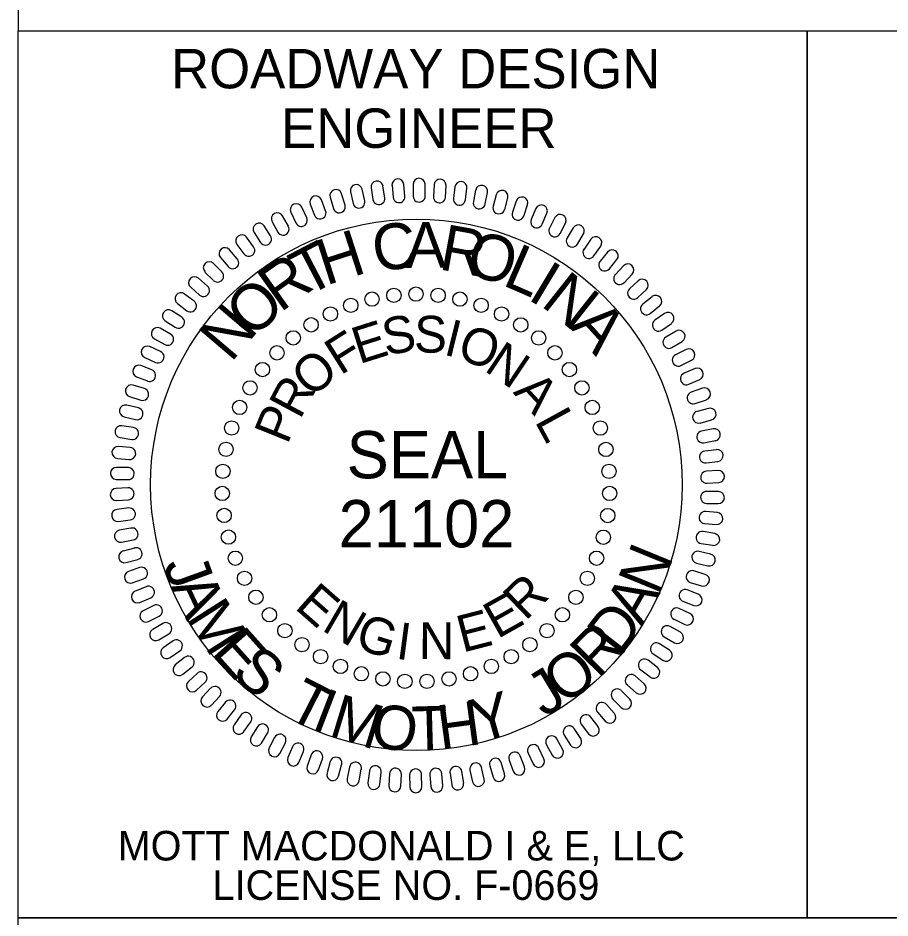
# Model space of a CAD drawing. Extents: x 1901670 to 1902225, y 193498 to 194278.
# Drawn here: x 1902112.54 to 1902123.59, y 194250.51 to 194261.92 of the extents above; entities that cross this region are included whole.
import ezdxf

# ---------------------------------------------------------------- set-up
doc = ezdxf.new("R2010")
doc.units = 0
for name, color, linetype in [('ENG SEALS CELL', 7, 'Continuous'), ('Old_Level_45', 7, 'Continuous'), ('Scratch_Level_3', 7, 'Continuous'), ('Sheet Border Standard 30in CELL', 7, 'Continuous'), ('Sheet Sticker Exception Certification CELL', 7, 'Continuous')]:
    doc.layers.add(name, color=color, linetype=linetype)

msp = doc.modelspace()

# ---------------------------------------------------------------- linework, layer by layer
at = {"layer": 'ENG SEALS CELL'}
for p, q in [((1902117.189, 194259.642), (1902117.166, 194259.789)), ((1902117.281, 194259.798), (1902117.293, 194259.649)), ((1902117.445, 194259.661), (1902117.432, 194259.811)), ((1902117.547, 194259.811), (1902117.549, 194259.661)), ((1902117.701, 194259.663), (1902117.699, 194259.813)), ((1902117.813, 194259.805), (1902117.805, 194259.656)), ((1902117.957, 194259.647), (1902117.965, 194259.797)), ((1902116.685, 194259.548), (1902116.642, 194259.692)), ((1902116.754, 194259.716), (1902116.788, 194259.57)), ((1902116.936, 194259.604), (1902116.902, 194259.75)), ((1902117.016, 194259.766), (1902117.039, 194259.618)), ((1902118.078, 194259.782), (1902118.06, 194259.633)), ((1902118.211, 194259.614), (1902118.229, 194259.762)), ((1902118.341, 194259.739), (1902118.312, 194259.593)), ((1902118.462, 194259.563), (1902118.491, 194259.71)), ((1902118.601, 194259.678), (1902118.562, 194259.534)), ((1902116.244, 194259.562), (1902116.298, 194259.422)), ((1902116.439, 194259.476), (1902116.386, 194259.616)), ((1902116.497, 194259.647), (1902116.539, 194259.504)), ((1902118.709, 194259.494), (1902118.748, 194259.639)), ((1902118.856, 194259.6), (1902118.807, 194259.458)), ((1902115.999, 194259.458), (1902116.061, 194259.322)), ((1902116.2, 194259.386), (1902116.136, 194259.522)), ((1902118.95, 194259.409), (1902119, 194259.55)), ((1902119.105, 194259.504), (1902119.046, 194259.365)), ((1902115.76, 194259.338), (1902115.833, 194259.206)), ((1902115.966, 194259.28), (1902115.894, 194259.411)), ((1902119.185, 194259.306), (1902119.245, 194259.444)), ((1902119.346, 194259.39), (1902119.278, 194259.257)), ((1902115.741, 194259.158), (1902115.66, 194259.284)), ((1902115.741, 194259.158), (1902115.66, 194259.284)), ((1902119.412, 194259.187), (1902119.481, 194259.321)), ((1902119.578, 194259.261), (1902119.501, 194259.132)), ((1902115.524, 194259.02), (1902115.435, 194259.141)), ((1902115.524, 194259.02), (1902115.435, 194259.141)), ((1902115.531, 194259.201), (1902115.613, 194259.075)), ((1902115.531, 194259.201), (1902115.613, 194259.075)), ((1902119.631, 194259.053), (1902119.709, 194259.182)), ((1902119.801, 194259.115), (1902119.716, 194258.991)), ((1902115.313, 194259.049), (1902115.403, 194258.929)), ((1902115.313, 194259.049), (1902115.403, 194258.929)), ((1902119.839, 194258.904), (1902119.926, 194259.026)), ((1902115.105, 194258.882), (1902115.203, 194258.769)), ((1902115.105, 194258.882), (1902115.203, 194258.769)), ((1902115.318, 194258.868), (1902115.22, 194258.982)), ((1902115.318, 194258.868), (1902115.22, 194258.982)), ((1902120.014, 194258.953), (1902119.919, 194258.837)), ((1902115.124, 194258.701), (1902115.018, 194258.808)), ((1902120.037, 194258.741), (1902120.132, 194258.857)), ((1902120.215, 194258.778), (1902120.112, 194258.668)), ((1902114.909, 194258.7), (1902115.015, 194258.595)), ((1902120.223, 194258.564), (1902120.326, 194258.674)), ((1902114.94, 194258.522), (1902114.828, 194258.621)), ((1902120.402, 194258.589), (1902120.292, 194258.487)), ((1902114.77, 194258.331), (1902114.651, 194258.421)), ((1902114.728, 194258.506), (1902114.84, 194258.408)), ((1902120.396, 194258.376), (1902120.506, 194258.478)), ((1902120.577, 194258.387), (1902120.46, 194258.294)), ((1902114.615, 194258.127), (1902114.489, 194258.209)), ((1902114.559, 194258.3), (1902114.679, 194258.209)), ((1902120.555, 194258.175), (1902120.672, 194258.269)), ((1902114.406, 194258.082), (1902114.531, 194258)), ((1902120.737, 194258.174), (1902120.613, 194258.088)), ((1902114.473, 194257.913), (1902114.342, 194257.987)), ((1902120.701, 194257.963), (1902120.823, 194258.049)), ((1902114.268, 194257.854), (1902114.399, 194257.781)), ((1902120.881, 194257.95), (1902120.753, 194257.873)), ((1902114.346, 194257.691), (1902114.211, 194257.754)), ((1902120.83, 194257.743), (1902120.959, 194257.819)), ((1902121.01, 194257.716), (1902120.876, 194257.649)), ((1902114.236, 194257.46), (1902114.096, 194257.514)), ((1902114.146, 194257.616), (1902114.281, 194257.553)), ((1902120.944, 194257.513), (1902121.078, 194257.581)), ((1902121.122, 194257.475), (1902120.983, 194257.417)), ((1902114.042, 194257.372), (1902114.181, 194257.318)), ((1902121.042, 194257.277), (1902121.181, 194257.335)), ((1902114.142, 194257.221), (1902113.999, 194257.265)), ((1902121.216, 194257.226), (1902121.074, 194257.177)), ((1902113.954, 194257.12), (1902114.097, 194257.075)), ((1902121.124, 194257.033), (1902121.266, 194257.081)), ((1902114.065, 194256.977), (1902113.919, 194257.01)), ((1902121.293, 194256.97), (1902121.148, 194256.932)), ((1902113.884, 194256.862), (1902114.03, 194256.829)), ((1902121.187, 194256.785), (1902121.332, 194256.824)), ((1902114.005, 194256.728), (1902113.856, 194256.751)), ((1902121.353, 194256.711), (1902121.205, 194256.683)), ((1902113.833, 194256.601), (1902113.981, 194256.577)), ((1902113.962, 194256.475), (1902113.813, 194256.488)), ((1902121.234, 194256.533), (1902121.381, 194256.562)), ((1902121.394, 194256.447), (1902121.245, 194256.429)), ((1902113.799, 194256.337), (1902113.948, 194256.323)), ((1902121.263, 194256.279), (1902121.412, 194256.296)), ((1902113.937, 194256.22), (1902113.788, 194256.222)), ((1902121.417, 194256.181), (1902121.267, 194256.174)), ((1902113.784, 194256.071), (1902113.934, 194256.067)), ((1902121.274, 194256.022), (1902121.424, 194256.03)), ((1902113.93, 194255.963), (1902113.781, 194255.956)), ((1902121.42, 194255.915), (1902121.27, 194255.918)), ((1902113.788, 194255.804), (1902113.938, 194255.811)), ((1902113.942, 194255.708), (1902113.793, 194255.69)), ((1902121.267, 194255.766), (1902121.417, 194255.763)), ((1902121.405, 194255.649), (1902121.256, 194255.663)), ((1902113.811, 194255.538), (1902113.96, 194255.556)), ((1902113.97, 194255.453), (1902113.823, 194255.425)), ((1902121.242, 194255.511), (1902121.391, 194255.498)), ((1902121.372, 194255.384), (1902121.224, 194255.408)), ((1902113.852, 194255.275), (1902113.999, 194255.303)), ((1902121.199, 194255.258), (1902121.348, 194255.235)), ((1902114.017, 194255.2), (1902113.872, 194255.162)), ((1902121.32, 194255.123), (1902121.174, 194255.157)), ((1902113.911, 194255.015), (1902114.056, 194255.053)), ((1902121.14, 194255.009), (1902121.286, 194254.975)), ((1902114.081, 194254.952), (1902113.939, 194254.904)), ((1902121.25, 194254.866), (1902121.108, 194254.91)), ((1902113.988, 194254.76), (1902114.13, 194254.808)), ((1902114.162, 194254.71), (1902114.024, 194254.651)), ((1902121.163, 194254.614), (1902121.023, 194254.668)), ((1902121.062, 194254.764), (1902121.206, 194254.72)), ((1902114.083, 194254.511), (1902114.221, 194254.57)), ((1902114.26, 194254.473), (1902114.126, 194254.405)), ((1902121.058, 194254.369), (1902120.922, 194254.432)), ((1902120.968, 194254.527), (1902121.108, 194254.473)), ((1902114.195, 194254.269), (1902114.329, 194254.336)), ((1902114.375, 194254.244), (1902114.246, 194254.166)), ((1902120.937, 194254.132), (1902120.806, 194254.205)), ((1902120.858, 194254.296), (1902120.994, 194254.232)), ((1902114.324, 194254.036), (1902114.452, 194254.112)), ((1902114.504, 194254.022), (1902114.381, 194253.936)), ((1902120.799, 194253.904), (1902120.673, 194253.986)), ((1902120.732, 194254.072), (1902120.863, 194253.999)), ((1902114.468, 194253.812), (1902114.591, 194253.897)), ((1902120.59, 194253.859), (1902120.715, 194253.777)), ((1902114.649, 194253.811), (1902114.532, 194253.717)), ((1902120.645, 194253.686), (1902120.526, 194253.777)), ((1902114.627, 194253.599), (1902114.745, 194253.693)), ((1902120.434, 194253.656), (1902120.553, 194253.565)), ((1902114.808, 194253.61), (1902114.699, 194253.508)), ((1902120.477, 194253.479), (1902120.364, 194253.578)), ((1902114.802, 194253.397), (1902114.911, 194253.499)), ((1902114.981, 194253.421), (1902114.879, 194253.312)), ((1902120.264, 194253.463), (1902120.377, 194253.365)), ((1902114.99, 194253.208), (1902115.092, 194253.317)), ((1902120.081, 194253.284), (1902120.186, 194253.178)), ((1902120.295, 194253.285), (1902120.188, 194253.391)), ((1902115.168, 194253.245), (1902115.073, 194253.128)), ((1902120.099, 194253.104), (1902120.001, 194253.217)), ((1902115.191, 194253.032), (1902115.285, 194253.149)), ((1902115.365, 194253.082), (1902115.278, 194252.959)), ((1902119.892, 194252.937), (1902119.801, 194253.056)), ((1902119.886, 194253.118), (1902119.984, 194253.004)), ((1902115.403, 194252.872), (1902115.489, 194252.994)), ((1902119.68, 194252.965), (1902119.77, 194252.846)), ((1902115.573, 194252.932), (1902115.496, 194252.805)), ((1902115.626, 194252.726), (1902115.703, 194252.854)), ((1902119.464, 194252.828), (1902119.545, 194252.702)), ((1902119.673, 194252.784), (1902119.591, 194252.91)), ((1902115.792, 194252.798), (1902115.724, 194252.665)), ((1902115.859, 194252.596), (1902115.928, 194252.729)), ((1902119.444, 194252.648), (1902119.371, 194252.779)), ((1902116.019, 194252.68), (1902115.96, 194252.542)), ((1902116.1, 194252.482), (1902116.159, 194252.62)), ((1902119.005, 194252.6), (1902119.068, 194252.464)), ((1902119.206, 194252.527), (1902119.143, 194252.663)), ((1902119.239, 194252.706), (1902119.31, 194252.574)), ((1902116.254, 194252.578), (1902116.205, 194252.436)), ((1902116.349, 194252.386), (1902116.398, 194252.528)), ((1902116.496, 194252.492), (1902116.457, 194252.348)), ((1902118.765, 194252.51), (1902118.818, 194252.37)), ((1902118.961, 194252.424), (1902118.907, 194252.564)), ((1902116.603, 194252.308), (1902116.642, 194252.452)), ((1902116.743, 194252.423), (1902116.713, 194252.276)), ((1902116.863, 194252.246), (1902116.891, 194252.394)), ((1902116.994, 194252.372), (1902116.975, 194252.223)), ((1902118.269, 194252.382), (1902118.302, 194252.236)), ((1902118.45, 194252.27), (1902118.417, 194252.416)), ((1902118.519, 194252.437), (1902118.562, 194252.294)), ((1902118.708, 194252.338), (1902118.664, 194252.481)), ((1902117.126, 194252.204), (1902117.145, 194252.353)), ((1902117.248, 194252.338), (1902117.239, 194252.188)), ((1902117.391, 194252.18), (1902117.4, 194252.33)), ((1902117.503, 194252.322), (1902117.506, 194252.172)), ((1902117.658, 194252.175), (1902117.655, 194252.325)), ((1902117.76, 194252.324), (1902117.773, 194252.175)), ((1902117.924, 194252.188), (1902117.911, 194252.337)), ((1902118.016, 194252.345), (1902118.038, 194252.196)), ((1902118.189, 194252.22), (1902118.166, 194252.368))]:
    msp.add_line(p, q, dxfattribs=at)
for centre in [(1902117.027, 194258.356), (1902117.304, 194258.404), (1902117.584, 194258.42), (1902117.865, 194258.404), (1902118.141, 194258.356), (1902116.758, 194258.277), (1902118.41, 194258.277), (1902116.5, 194258.168), (1902118.669, 194258.167), (1902116.255, 194258.03), (1902118.913, 194258.029), (1902116.028, 194257.865), (1902119.14, 194257.864), (1902115.822, 194257.675), (1902119.346, 194257.675), (1902115.638, 194257.463), (1902119.53, 194257.463), (1902115.48, 194257.231), (1902119.688, 194257.231), (1902115.349, 194256.983), (1902119.819, 194256.983), (1902115.247, 194256.722), (1902119.921, 194256.721), (1902115.176, 194256.451), (1902119.992, 194256.45), (1902115.136, 194256.173), (1902120.032, 194256.172), (1902115.128, 194255.892), (1902120.04, 194255.892), (1902115.152, 194255.613), (1902120.016, 194255.612), (1902115.207, 194255.338), (1902119.96, 194255.337), (1902115.294, 194255.071), (1902119.874, 194255.071), (1902115.411, 194254.816), (1902119.757, 194254.815), (1902115.555, 194254.576), (1902119.612, 194254.575), (1902115.727, 194254.353), (1902119.441, 194254.353), (1902115.922, 194254.152), (1902119.245, 194254.152), (1902116.139, 194253.975), (1902119.028, 194253.974), (1902116.375, 194253.823), (1902118.792, 194253.823), (1902116.627, 194253.699), (1902118.54, 194253.699), (1902116.891, 194253.605), (1902117.165, 194253.541), (1902118.003, 194253.541), (1902118.276, 194253.605), (1902117.443, 194253.509), (1902117.724, 194253.509)]:
    msp.add_circle(centre, 0.091, dxfattribs=at)
for centre, start, end in [((1902116.828, 194259.733), 12.8349, 192.8343), ((1902117.091, 194259.778), 8.8349, 188.8343), ((1902117.356, 194259.804), 4.8349, 184.8343), ((1902117.623, 194259.812), 0.8349, 180.8343), ((1902117.889, 194259.801), 356.8349, 176.8343), ((1902118.154, 194259.772), 352.8349, 172.8343), ((1902118.416, 194259.724), 348.8349, 168.8343), ((1902116.569, 194259.67), 16.8349, 196.8343), ((1902118.675, 194259.659), 344.8349, 164.8343), ((1902116.067, 194259.49), 24.8349, 204.8343), ((1902116.315, 194259.589), 20.8349, 200.8343), ((1902116.861, 194259.587), 192.8343, 12.8349), ((1902117.114, 194259.63), 188.8343, 8.8349), ((1902117.369, 194259.655), 184.8343, 4.8349), ((1902117.625, 194259.662), 180.8343, 0.8349), ((1902117.881, 194259.652), 176.8343, 356.8349), ((1902118.135, 194259.623), 172.8343, 352.8349), ((1902118.387, 194259.577), 168.8343, 348.8349), ((1902118.928, 194259.575), 340.8349, 160.8343), ((1902115.827, 194259.375), 28.8349, 208.8343), ((1902116.368, 194259.449), 200.8343, 20.8349), ((1902116.612, 194259.526), 196.8343, 16.8349), ((1902118.635, 194259.514), 164.8343, 344.8349), ((1902118.878, 194259.433), 160.8343, 340.8349), ((1902119.174, 194259.474), 336.8349, 156.8343), ((1902116.13, 194259.354), 204.8343, 24.8349), ((1902119.115, 194259.336), 156.8343, 336.8349), ((1902119.413, 194259.355), 332.8349, 152.8343), ((1902115.596, 194259.243), 32.8349, 212.8343), ((1902115.596, 194259.243), 32.8349, 212.8343), ((1902115.899, 194259.243), 208.8343, 28.8349), ((1902119.345, 194259.222), 152.8343, 332.8349), ((1902119.643, 194259.221), 328.8349, 148.8343), ((1902115.374, 194259.095), 36.8349, 216.8343), ((1902115.374, 194259.095), 36.8349, 216.8343), ((1902115.677, 194259.117), 212.8343, 32.8349), ((1902115.677, 194259.117), 212.8343, 32.8349), ((1902119.566, 194259.093), 148.8343, 328.8349), ((1902119.864, 194259.071), 324.8349, 144.8343), ((1902115.163, 194258.932), 40.8349, 220.8343), ((1902115.163, 194258.932), 40.8349, 220.8343), ((1902115.464, 194258.975), 216.8343, 36.8349), ((1902115.464, 194258.975), 216.8343, 36.8349), ((1902119.777, 194258.948), 144.8343, 324.8349), ((1902120.073, 194258.905), 320.8349, 140.8343), ((1902114.964, 194258.754), 44.8349, 224.8343), ((1902115.261, 194258.818), 220.8343, 40.8349), ((1902115.261, 194258.818), 220.8343, 40.8349), ((1902119.978, 194258.789), 140.8343, 320.8349), ((1902120.27, 194258.726), 316.8349, 136.8343), ((1902115.069, 194258.648), 224.8343, 44.8349), ((1902120.167, 194258.617), 136.8343, 316.8349), ((1902114.778, 194258.564), 48.8349, 228.8343), ((1902120.454, 194258.533), 312.8349, 132.8343), ((1902114.605, 194258.36), 52.8349, 232.8343), ((1902114.89, 194258.465), 228.8343, 48.8349), ((1902120.344, 194258.431), 132.8343, 312.8349), ((1902114.725, 194258.27), 232.8343, 52.8349), ((1902120.624, 194258.328), 308.8349, 128.8343), ((1902114.447, 194258.145), 56.8349, 236.8343), ((1902120.508, 194258.234), 128.8343, 308.8349), ((1902114.573, 194258.063), 236.8343, 56.8349), ((1902120.657, 194258.026), 124.8343, 304.8349), ((1902120.78, 194258.112), 304.8349, 124.8343), ((1902114.305, 194257.92), 60.8349, 240.8343), ((1902120.92, 194257.885), 300.8349, 120.8343), ((1902114.436, 194257.847), 240.8343, 60.8349), ((1902120.791, 194257.808), 120.8343, 300.8349), ((1902114.178, 194257.685), 64.8349, 244.8343), ((1902114.314, 194257.622), 244.8343, 64.8349), ((1902120.91, 194257.581), 116.8343, 296.8349), ((1902121.044, 194257.649), 296.8349, 116.8343), ((1902114.069, 194257.442), 68.8349, 248.8343), ((1902114.208, 194257.388), 248.8343, 68.8349), ((1902121.013, 194257.346), 112.8343, 292.8349), ((1902121.151, 194257.405), 292.8349, 112.8343), ((1902113.976, 194257.192), 72.8349, 252.8343), ((1902114.119, 194257.148), 252.8343, 72.8349), ((1902121.099, 194257.105), 108.8343, 288.8349), ((1902121.241, 194257.154), 288.8349, 108.8343), ((1902113.901, 194256.937), 76.8349, 256.8343), ((1902114.047, 194256.902), 256.8343, 76.8349), ((1902121.313, 194256.897), 284.8349, 104.8343), ((1902121.168, 194256.859), 104.8343, 284.8349), ((1902113.844, 194256.676), 80.8349, 260.8343), ((1902113.992, 194256.652), 260.8343, 80.8349), ((1902121.367, 194256.636), 280.8349, 100.8343), ((1902121.22, 194256.608), 100.8343, 280.8349), ((1902113.806, 194256.412), 84.8349, 264.8343), ((1902113.955, 194256.399), 264.8343, 84.8349), ((1902121.254, 194256.354), 96.8343, 276.8349), ((1902121.403, 194256.372), 276.8349, 96.8343), ((1902113.786, 194256.147), 88.8349, 268.8343), ((1902113.936, 194256.143), 268.8343, 88.8349), ((1902121.27, 194256.098), 92.8343, 272.8349), ((1902121.42, 194256.106), 272.8349, 92.8343), ((1902113.785, 194255.88), 92.8349, 272.8343), ((1902113.934, 194255.887), 272.8343, 92.8349), ((1902121.269, 194255.842), 88.8343, 268.8349), ((1902121.418, 194255.839), 268.8349, 88.8343), ((1902113.802, 194255.614), 96.8349, 276.8343), ((1902113.951, 194255.632), 276.8343, 96.8349), ((1902121.249, 194255.587), 84.8343, 264.8349), ((1902121.398, 194255.573), 264.8349, 84.8343), ((1902113.985, 194255.378), 280.8343, 100.8349), ((1902113.837, 194255.35), 100.8349, 280.8343), ((1902121.212, 194255.333), 80.8343, 260.8349), ((1902121.36, 194255.309), 260.8349, 80.8343), ((1902113.891, 194255.089), 104.8349, 284.8343), ((1902114.036, 194255.127), 284.8343, 104.8349), ((1902121.157, 194255.083), 76.8343, 256.8349), ((1902121.303, 194255.049), 256.8349, 76.8343), ((1902113.964, 194254.832), 108.8349, 288.8343), ((1902114.105, 194254.88), 288.8343, 108.8349), ((1902121.085, 194254.837), 72.8343, 252.8349), ((1902121.228, 194254.793), 252.8349, 72.8343), ((1902114.192, 194254.639), 292.8343, 112.8349), ((1902120.996, 194254.597), 68.8343, 248.8349), ((1902114.053, 194254.581), 112.8349, 292.8343), ((1902121.136, 194254.543), 248.8349, 68.8343), ((1902114.294, 194254.405), 296.8343, 116.8349), ((1902120.89, 194254.364), 64.8343, 244.8349), ((1902114.16, 194254.337), 116.8349, 296.8343), ((1902121.026, 194254.3), 244.8349, 64.8343), ((1902114.413, 194254.178), 300.8343, 120.8349), ((1902120.769, 194254.139), 60.8343, 240.8349), ((1902114.284, 194254.101), 120.8349, 300.8343), ((1902120.9, 194254.066), 240.8349, 60.8343), ((1902114.547, 194253.96), 304.8343, 124.8349), ((1902120.632, 194253.922), 56.8343, 236.8349), ((1902114.424, 194253.874), 124.8349, 304.8343), ((1902120.757, 194253.84), 236.8349, 56.8343), ((1902114.697, 194253.752), 308.8343, 128.8349), ((1902120.48, 194253.716), 52.8343, 232.8349), ((1902114.58, 194253.658), 128.8349, 308.8343), ((1902114.86, 194253.554), 312.8343, 132.8349), ((1902120.599, 194253.625), 232.8349, 52.8343), ((1902120.314, 194253.521), 48.8343, 228.8349), ((1902114.75, 194253.452), 132.8349, 312.8343), ((1902115.037, 194253.369), 316.8343, 136.8349), ((1902120.135, 194253.338), 44.8343, 224.8349), ((1902120.427, 194253.422), 228.8349, 48.8343), ((1902114.934, 194253.26), 136.8349, 316.8343), ((1902120.241, 194253.231), 224.8349, 44.8343), ((1902115.226, 194253.196), 320.8343, 140.8349), ((1902119.943, 194253.167), 40.8343, 220.8349), ((1902115.132, 194253.08), 140.8349, 320.8343), ((1902115.427, 194253.038), 324.8343, 144.8349), ((1902119.741, 194253.011), 36.8343, 216.8349), ((1902120.042, 194253.054), 220.8349, 40.8343), ((1902115.341, 194252.915), 144.8349, 324.8343), ((1902115.639, 194252.893), 328.8343, 148.8349), ((1902119.527, 194252.869), 32.8343, 212.8349), ((1902115.86, 194252.764), 332.8343, 152.8349), ((1902119.831, 194252.891), 216.8349, 36.8343), ((1902115.561, 194252.765), 148.8349, 328.8343), ((1902116.089, 194252.65), 336.8343, 156.8349), ((1902119.305, 194252.742), 28.8343, 208.8349), ((1902119.609, 194252.743), 212.8349, 32.8343), ((1902115.791, 194252.63), 152.8349, 332.8343), ((1902116.326, 194252.552), 340.8343, 160.8349), ((1902118.836, 194252.537), 20.8343, 200.8349), ((1902119.074, 194252.631), 24.8343, 204.8349), ((1902119.377, 194252.611), 208.8349, 28.8343), ((1902116.03, 194252.512), 156.8349, 336.8343), ((1902116.569, 194252.472), 344.8343, 164.8349), ((1902116.817, 194252.408), 348.8343, 168.8349), ((1902118.592, 194252.459), 16.8343, 196.8349), ((1902119.137, 194252.495), 204.8349, 24.8343), ((1902116.277, 194252.411), 160.8349, 340.8343), ((1902117.069, 194252.362), 352.8343, 172.8349), ((1902117.324, 194252.334), 356.8343, 176.8349), ((1902117.58, 194252.323), 0.8343, 180.8349), ((1902117.836, 194252.331), 4.8343, 184.8349), ((1902118.09, 194252.356), 8.8343, 188.8349), ((1902118.343, 194252.399), 12.8343, 192.8349), ((1902118.889, 194252.397), 200.8349, 20.8343), ((1902116.53, 194252.327), 164.8349, 344.8343), ((1902116.788, 194252.261), 168.8349, 348.8343), ((1902118.376, 194252.253), 192.8349, 12.8343), ((1902118.635, 194252.316), 196.8349, 16.8343), ((1902117.05, 194252.214), 172.8349, 352.8343), ((1902117.315, 194252.184), 176.8349, 356.8343), ((1902117.582, 194252.174), 180.8349, 0.8343), ((1902117.848, 194252.181), 184.8349, 4.8343), ((1902118.113, 194252.208), 188.8349, 8.8343)]:
    msp.add_arc(centre, 0.0761, start, end, dxfattribs=at)
at = {"layer": 'Scratch_Level_3'}
msp.add_circle((1902117.59, 194256.002), 3.37, dxfattribs=at)
at = {"layer": 'Sheet Border Standard 30in CELL'}
for p, q in [((1902112.539, 194263.009), (1902112.539, 194261.759)), ((1902122.544, 194261.759), (1902122.544, 194250.514))]:
    msp.add_line(p, q, dxfattribs=at)
for points in [[(1902112.539, 194261.759), (1902122.544, 194261.759), (1902122.544, 194250.509), (1902112.539, 194250.509)], [(1902122.544, 194261.759), (1902132.544, 194261.759), (1902132.544, 194250.509), (1902122.544, 194250.509)]]:
    msp.add_lwpolyline(points, close=True, dxfattribs=at)
at = {"layer": 'Sheet Sticker Exception Certification CELL'}
for p, q in [((1902112.539, 194248.159), (1902112.539, 194250.509)), ((1902112.539, 194250.509), (1902132.542, 194250.509))]:
    msp.add_line(p, q, dxfattribs=at)

# ---------------------------------------------------------------- texts
at = {"layer": 'ENG SEALS CELL'}
for s, height, rotation, p in [('C', 0.582, 7.9778, (1902117.071, 194258.698)), ('A', 0.582, 0.1945, (1902117.45, 194258.752)), ('H', 0.582, 17.8424, (1902116.442, 194258.525)), ('R', 0.582, 349.6661, (1902117.861, 194258.737)), ('T', 0.582, 27.6116, (1902116.195, 194258.38)), ('O', 0.582, 345.727, (1902118.192, 194258.673)), ('L', 0.582, 336.5157, (1902118.665, 194258.54)), ('R', 0.582, 35.4408, (1902115.861, 194258.178)), ('I', 0.582, 328.9592, (1902118.984, 194258.363)), ('N', 0.582, 321.6624, (1902119.152, 194258.282)), ('O', 0.582, 42.8836, (1902115.511, 194257.842)), ('N', 0.582, 49.6124, (1902115.237, 194257.542)), ('A', 0.582, 312.1327, (1902119.521, 194258.004)), ('E', 0.467, 17.5898, (1902116.864, 194257.529)), ('S', 0.467, 10.2172, (1902117.2, 194257.639)), ('S', 0.467, 359.0087, (1902117.557, 194257.681)), ('I', 0.467, 346.1383, (1902117.921, 194257.655)), ('F', 0.467, 32.3349, (1902116.627, 194257.384)), ('O', 0.467, 340.1508, (1902118.084, 194257.612)), ('N', 0.467, 326.0425, (1902118.436, 194257.455)), ('O', 0.467, 40.6085, (1902116.26, 194257.093)), ('R', 0.467, 61.8256, (1902116.114, 194256.819)), ('A', 0.467, 312.7467, (1902118.807, 194257.17)), ('P', 0.467, 68.0589, (1902115.955, 194256.502)), ('L', 0.467, 298.716, (1902119.084, 194256.809)), ('SEAL', 0.5992, 360, (1902116.705, 194256.084)), ('N', 0.56, 67.7218, (1902120.652, 194254.588)), ('J', 0.56, 289.9696, (1902114.372, 194254.99)), ('R', 0.467, 44.0241, (1902118.971, 194254.268)), ('A', 0.56, 294.9909, (1902114.473, 194254.712)), ('E', 0.467, 318.6101, (1902116.034, 194254.441)), ('A', 0.56, 60.2523, (1902120.442, 194254.202)), ('M', 0.56, 302.4603, (1902114.667, 194254.318)), ('N', 0.467, 329.8446, (1902116.376, 194254.163)), ('E', 0.467, 29.2789, (1902118.617, 194254.042)), ('D', 0.56, 52.0752, (1902120.157, 194253.814)), ('G', 0.467, 342.6124, (1902116.795, 194253.934)), ('E', 0.467, 14.5337, (1902118.175, 194253.872)), ('I', 0.467, 352.4162, (1902117.319, 194253.799)), ('N', 0.467, 359.7887, (1902117.619, 194253.792)), ('R', 0.56, 45.5352, (1902119.891, 194253.536)), ('E', 0.56, 311.7676, (1902114.978, 194253.867)), ('S', 0.56, 318.0541, (1902115.227, 194253.594)), ('O', 0.56, 36.2069, (1902119.461, 194253.196)), ('J', 0.56, 31.1856, (1902119.208, 194253.043)), ('T', 0.56, 332.8874, (1902115.922, 194253.07)), ('I', 0.56, 338.9627, (1902116.242, 194252.91)), ('M', 0.56, 342.9891, (1902116.462, 194252.823)), ('Y', 0.56, 15.9509, (1902118.374, 194252.721)), ('O', 0.56, 352.2963, (1902116.991, 194252.682)), ('T', 0.56, 1.6246, (1902117.537, 194252.629)), ('H', 0.56, 7.6999, (1902117.895, 194252.643))]:
    msp.add_text(s, height=height, rotation=rotation, dxfattribs=at).set_placement(p)
msp.add_text('21102', height=0.5994, dxfattribs=at).set_placement((1902116.603, 194255.209))
at = {"layer": 'Old_Level_45'}
for s, p in [('MOTT MACDONALD I & E, LLC', (1902113.803, 194251.238)), (' LICENSE NO. F-0669', (1902114.866, 194250.738))]:
    msp.add_text(s, height=0.375, rotation=360, dxfattribs=at).set_placement(p)
at = {"layer": 'Sheet Border Standard 30in CELL'}
for s, height, p in [('ROADWAY DESIGN', 0.50001, (1902114.479, 194261.029)), ('ENGINEER', 0.5, (1902115.874, 194260.274))]:
    msp.add_text(s, height=height, dxfattribs=at).set_placement(p)

doc.saveas('drawing.dxf')
